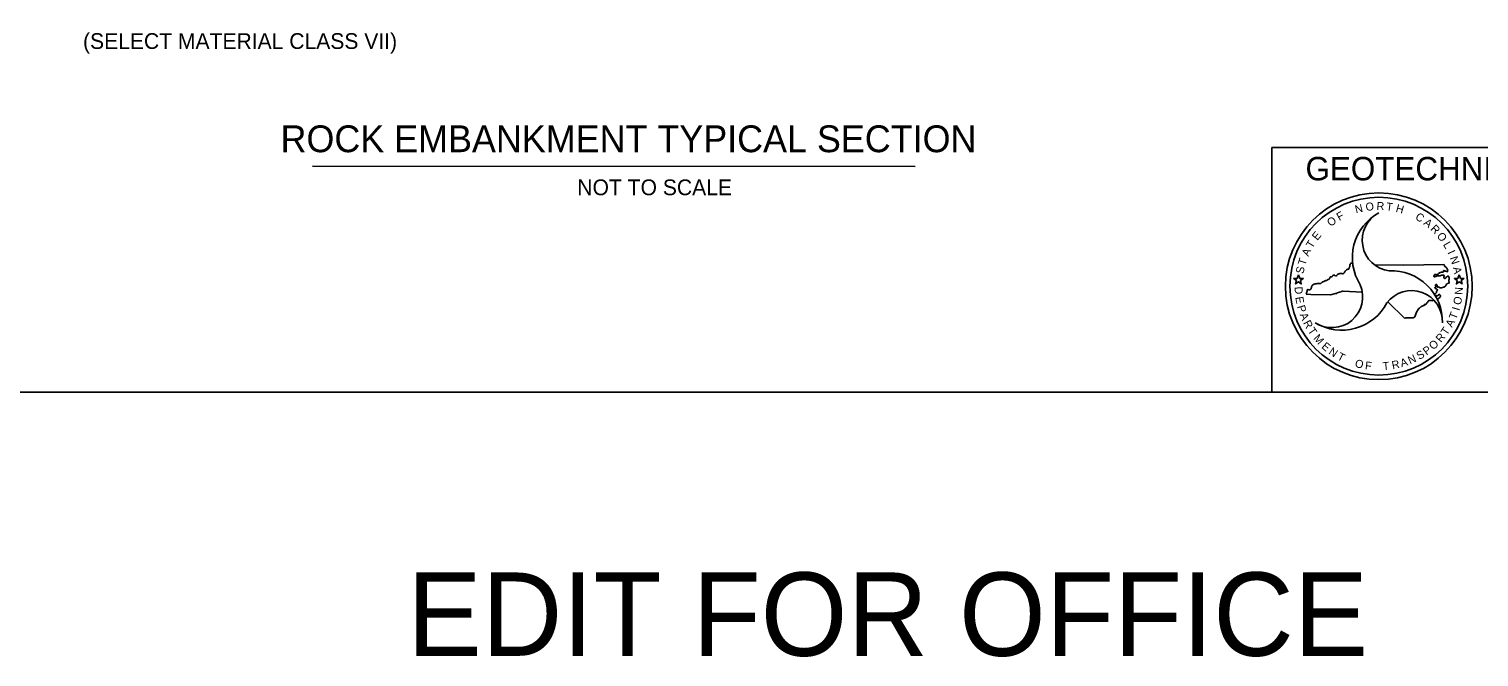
# Model space of a CAD drawing. Extents: x 2189223 to 2190097, y 563994 to 564498.
# Drawn here: x 2189459.3 to 2189702.6, y 563994.5 to 564099.9 of the extents above; entities that cross this region are included whole.
import ezdxf

# ---------------------------------------------------------------- set-up
doc = ezdxf.new("R2010")
doc.units = 0
for name, color, linetype in [('Default', 7, 'Continuous'), ('Geotech Sheets and Borders Cell', 7, 'Continuous'), ('Old_Level_2', 7, 'Continuous')]:
    doc.layers.add(name, color=color, linetype=linetype)

msp = doc.modelspace()

# ---------------------------------------------------------------- linework, layer by layer
at = {"layer": 'Default'}
msp.add_lwpolyline([(2189347.77, 564405.93), (2189877.15, 564405.93), (2189877.15, 564038.89), (2189347.77, 564038.89)], close=True, dxfattribs=at)
at = {"layer": 'Geotech Sheets and Borders Cell'}
for p, q in [((2189681.03, 564060.53), (2189681.38, 564060.53)), ((2189685.12, 564060.28), (2189689.93, 564060.22)), ((2189689.93, 564060.22), (2189696.68, 564060.33)), ((2189674.37, 564055.32), (2189673.59, 564055.37)), ((2189677.65, 564055.23), (2189674.37, 564055.32)), ((2189678.5, 564055.49), (2189677.65, 564055.23)), ((2189678.72, 564055.46), (2189678.5, 564055.49)), ((2189678.78, 564055.6), (2189678.72, 564055.46)), ((2189679.53, 564055.78), (2189678.78, 564055.6)), ((2189679.61, 564055.89), (2189679.53, 564055.78)), ((2189679.72, 564055.84), (2189679.61, 564055.89)), ((2189683, 564055.66), (2189679.72, 564055.84)), ((2189690.11, 564051.29), (2189687.29, 564054.08))]:
    msp.add_line(p, q, dxfattribs=at)
for points in [[(2189667.83, 564079.96), (2189782.41, 564079.96), (2189782.41, 564038.89), (2189667.83, 564038.89)], [(2189672.28, 564058.6), (2189672.04, 564058), (2189671.48, 564058), (2189671.94, 564057.63), (2189671.8, 564057.06), (2189672.27, 564057.42), (2189672.76, 564057.06), (2189672.61, 564057.63), (2189673.07, 564058), (2189672.52, 564058)], [(2189699.25, 564058.6), (2189699.49, 564058), (2189700.04, 564058), (2189699.58, 564057.63), (2189699.73, 564057.06), (2189699.25, 564057.42), (2189698.77, 564057.06), (2189698.91, 564057.63), (2189698.45, 564058), (2189699.01, 564058)]]:
    msp.add_lwpolyline(points, close=True, dxfattribs=at)
for centre, radius in [((2189685.76, 564056.68), 15.67), ((2189685.76, 564056.69), 14.92)]:
    msp.add_circle(centre, radius, dxfattribs=at)
for centre, major_axis, start_param, end_param in [((2189689.91, 564061.49), (-8.59, 0), 5.216686, 6.845651), ((2189688.15, 564064.41), (-5.18, 0), 5.190489, 7.730961), ((2189687.85, 564050.7), (8.59, 0), 6.263884, 7.892848), ((2189677.88, 564054.9), (5.18, 0), 4.14305, 6.68389), ((2189691.26, 564050.77), (5.18, 0), 6.237699, 8.777986), ((2189679.53, 564057.89), (8.59, 0), 4.169489, 5.798453)]:
    msp.add_ellipse(centre, major_axis=major_axis, ratio=0.999319, start_param=start_param, end_param=end_param, dxfattribs=at)
for points in [[(2189673.59, 564055.37), (2189673.65, 564055.58), (2189673.69, 564055.77), (2189673.75, 564055.94), (2189673.81, 564056.13), (2189673.89, 564056.12), (2189674.03, 564056.08), (2189674.16, 564056.1), (2189674.29, 564056.15), (2189674.39, 564056.25), (2189674.45, 564056.45), (2189674.47, 564056.62), (2189674.57, 564056.78), (2189674.81, 564057), (2189675.08, 564057.07), (2189675.41, 564057.12), (2189675.77, 564057.12), (2189676.04, 564057.17), (2189676.28, 564057.34), (2189676.51, 564057.46), (2189676.76, 564057.6), (2189677.02, 564057.66), (2189677.27, 564057.83), (2189677.46, 564057.93), (2189677.52, 564058.05), (2189677.56, 564058.16), (2189677.59, 564058.24), (2189677.67, 564058.26), (2189677.81, 564058.22), (2189677.95, 564058.33), (2189678, 564058.42), (2189678.14, 564058.52), (2189678.25, 564058.57), (2189678.33, 564058.55), (2189678.4, 564058.44), (2189678.47, 564058.39), (2189678.56, 564058.41), (2189678.69, 564058.47), (2189678.76, 564058.58), (2189678.95, 564058.71), (2189679.12, 564058.77), (2189679.35, 564058.82), (2189679.55, 564058.82), (2189679.64, 564058.79), (2189679.79, 564058.78), (2189679.88, 564058.86), (2189680.03, 564059.05), (2189680.13, 564059.19), (2189680.36, 564059.43), (2189680.54, 564059.53), (2189680.64, 564059.56), (2189680.75, 564059.6), (2189680.78, 564059.72), (2189680.8, 564059.8), (2189680.83, 564059.89), (2189680.91, 564060), (2189680.9, 564060.08), (2189680.9, 564060.24), (2189681.04, 564060.52)], [(2189696.68, 564060.33), (2189696.68, 564060.31), (2189696.77, 564060.19), (2189696.8, 564060.08), (2189696.95, 564059.94), (2189697.07, 564059.87), (2189697.15, 564059.7), (2189697.24, 564059.58), (2189697.31, 564059.24), (2189697.24, 564059.16), (2189697.28, 564059.11), (2189697.17, 564059.13), (2189697.13, 564059.24), (2189696.95, 564059.22), (2189696.8, 564059.25), (2189696.69, 564059.34), (2189696.6, 564059.31), (2189696.65, 564059.18), (2189696.61, 564059.09), (2189696.44, 564059.06), (2189696.11, 564058.98), (2189695.95, 564058.94), (2189695.79, 564058.81), (2189695.51, 564058.62), (2189695.33, 564058.65), (2189695.18, 564058.63), (2189695.12, 564058.64), (2189695.06, 564058.53), (2189694.99, 564058.4), (2189694.97, 564058.33), (2189695.04, 564058.28), (2189695.21, 564058.29), (2189695.46, 564058.38), (2189695.61, 564058.42), (2189695.92, 564058.44), (2189696.06, 564058.45), (2189696.32, 564058.56), (2189696.57, 564058.52), (2189696.7, 564058.49), (2189696.74, 564058.41), (2189696.69, 564058.29), (2189696.65, 564058.18), (2189696.68, 564058.08), (2189696.78, 564057.97), (2189696.94, 564058.01), (2189697, 564058.12), (2189697.15, 564058.26), (2189697.29, 564058.38), (2189697.4, 564058.37), (2189697.48, 564058.34), (2189697.52, 564058.19), (2189697.58, 564058), (2189697.54, 564057.81), (2189697.52, 564057.62), (2189697.53, 564057.48), (2189697.57, 564057.31), (2189697.54, 564057.22), (2189697.42, 564057.18), (2189697.29, 564057.13), (2189697.19, 564057.07), (2189697.13, 564057.02), (2189697.03, 564056.83), (2189696.97, 564056.7), (2189696.84, 564056.62), (2189696.67, 564056.54), (2189696.48, 564056.5)], [(2189696.48, 564056.5), (2189696.25, 564056.39), (2189696.04, 564056.44), (2189695.89, 564056.52), (2189695.81, 564056.52), (2189695.68, 564056.6), (2189695.62, 564056.53), (2189695.56, 564056.54), (2189695.54, 564056.67), (2189695.53, 564056.76), (2189695.54, 564056.87), (2189695.48, 564056.95), (2189695.38, 564057), (2189695.3, 564056.95), (2189695.29, 564056.79), (2189695.3, 564056.68), (2189695.29, 564056.55), (2189695.21, 564056.44), (2189695.16, 564056.49), (2189695.26, 564056.28), (2189695.43, 564056.23), (2189695.58, 564055.99), (2189695.47, 564055.89), (2189695.41, 564055.79), (2189695.44, 564055.73), (2189695.47, 564055.66), (2189695.37, 564055.56), (2189695.31, 564055.49), (2189695.13, 564055.33), (2189695.1, 564055.31)], [(2189695.59, 564054.44), (2189695.69, 564054.53), (2189695.89, 564054.71), (2189696.13, 564055.08), (2189696.07, 564055.19), (2189695.97, 564055.27), (2189695.87, 564055.33), (2189695.77, 564055.18), (2189695.55, 564055.09), (2189695.28, 564055.02)], [(2189695.02, 564054.33), (2189694.94, 564054.33), (2189694.74, 564054.26), (2189694.42, 564054.3), (2189694.19, 564054.29), (2189694.03, 564054.15), (2189693.91, 564053.97), (2189693.76, 564053.79), (2189693.62, 564053.63), (2189693.51, 564053.63), (2189693.42, 564053.62), (2189693.39, 564053.53), (2189693.43, 564053.5), (2189693.27, 564053.45), (2189693.05, 564053.35), (2189692.85, 564053.26), (2189692.7, 564053.11), (2189692.5, 564052.94), (2189692.26, 564052.61), (2189692.1, 564052.35), (2189691.94, 564051.91), (2189691.82, 564051.6), (2189691.65, 564051.45), (2189691.37, 564051.36), (2189691.18, 564051.36), (2189690.83, 564051.39), (2189690.53, 564051.38), (2189690.26, 564051.37), (2189690.11, 564051.29)]]:
    msp.add_spline(points, degree=3, dxfattribs=at)
at = {"layer": 'Old_Level_2'}
msp.add_line((2189607.98, 564076.76), (2189506.87, 564076.81), dxfattribs=at)

# ---------------------------------------------------------------- texts
at = {"layer": 'Default'}
for s, height, p in [('(SELECT MATERIAL CLASS VII)', 2.6459, (2189468.36, 564096.51)), ('ROCK EMBANKMENT TYPICAL SECTION', 4.5024, (2189501.5, 564079.18)), ('NOT TO SCALE', 2.6459, (2189551.29, 564071.96))]:
    msp.add_text(s, height=height, dxfattribs=at).set_placement(p)
at = {"layer": 'Geotech Sheets and Borders Cell'}
for s, height, rotation, p in [('GEOTECHNICAL ENGINEERING UNIT', 3.9375, 360, (2189673.46, 564074.45)), ('N', 1.34, 14.2209, (2189681.94, 564068.9)), ('O', 1.34, 6.5073, (2189683.62, 564069.31)), ('R', 1.34, 359.0508, (2189685.38, 564069.48)), ('T', 1.34, 351.9427, (2189686.93, 564069.43)), ('H', 1.34, 344.2842, (2189688.51, 564069.19)), ('O', 1.34, 35.9791, (2189677.67, 564066.61)), ('F', 1.34, 28.8913, (2189679.12, 564067.63)), ('C', 1.34, 329.1608, (2189691.76, 564067.99)), ('A', 1.34, 322.0539, (2189693.16, 564067.13)), ('E', 1.34, 50.9542, (2189675.45, 564064.27)), ('R', 1.34, 315.2024, (2189694.33, 564066.21)), ('O', 1.34, 307.8826, (2189695.41, 564065.1)), ('A', 1.34, 64.9783, (2189673.94, 564061.59)), ('T', 1.34, 57.9626, (2189674.58, 564062.93)), ('L', 1.34, 300.3686, (2189696.48, 564063.69)), ('I', 1.34, 294.8085, (2189697.24, 564062.36)), ('T', 1.34, 71.9105, (2189673.41, 564060.07)), ('N', 1.34, 288.7743, (2189697.65, 564061.45)), ('S', 1.34, 78.3847, (2189673.11, 564058.69)), ('A', 1.34, 281.7063, (2189698.18, 564059.81)), ('D', 1.34, 273.2739, (2189671.62, 564056.59)), ('N', 1.34, 86.8701, (2189699.83, 564055.21)), ('E', 1.34, 279.9473, (2189671.74, 564054.83)), ('P', 1.34, 285.9916, (2189672.03, 564053.3)), ('I', 1.34, 73.9857, (2189699.27, 564052.5)), ('O', 1.34, 79.7053, (2189699.53, 564053.47)), ('A', 1.34, 291.9497, (2189672.45, 564051.92)), ('R', 1.34, 298.1759, (2189673.02, 564050.55)), ('A', 1.34, 62.7186, (2189698.05, 564049.68)), ('T', 1.34, 68.9016, (2189698.72, 564051)), ('T', 1.34, 304.6168, (2189673.77, 564049.2)), ('M', 1.34, 311.8434, (2189674.69, 564047.89)), ('R', 1.34, 50.0202, (2189696.19, 564047.14)), ('T', 1.34, 56.4249, (2189697.17, 564048.33)), ('E', 1.34, 318.996, (2189676.04, 564046.42)), ('N', 1.34, 325.7321, (2189677.23, 564045.42)), ('T', 1.34, 332.5903, (2189678.66, 564044.46)), ('S', 1.34, 30.6529, (2189692.55, 564044.29)), ('P', 1.34, 36.4365, (2189693.76, 564045.04)), ('O', 1.34, 43.1917, (2189694.91, 564045.91)), ('O', 1.34, 346.049, (2189681.66, 564043.16)), ('F', 1.34, 352.5694, (2189683.39, 564042.76)), ('T', 1.34, 5.6562, (2189686.48, 564042.57)), ('R', 1.34, 11.9114, (2189688.08, 564042.75)), ('A', 1.34, 18.0071, (2189689.59, 564043.08)), ('N', 1.34, 24.4382, (2189691, 564043.56))]:
    msp.add_text(s, height=height, rotation=rotation, dxfattribs=at).set_placement(p)
msp.add_text('EDIT FOR OFFICE', height=14, dxfattribs=at).set_placement((2189522.77, 563994.65))

doc.saveas('drawing.dxf')
